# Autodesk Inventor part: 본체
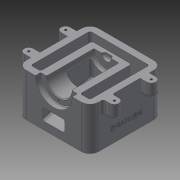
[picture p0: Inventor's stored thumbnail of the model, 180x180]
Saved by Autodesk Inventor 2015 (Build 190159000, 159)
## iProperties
Created: 2022-03
Part Number: 본체
Material: 일반
Document SubType Name: Modeling
Designer: pc-04
Density: 1 g/cm^3
Appearance: 기본값
Author: pc-04
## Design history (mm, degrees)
sketch "스케치1"
  geometry: L1 (-42, 55)-(42, 55); L2 (55, 42)-(55, -42); L3 (42, -55)-(-42, -55); L4 (-55, -42)-(-55, 42); L5 (-55, 55)-(55, -55); L6 (55, 55)-(-55, -55); A1 r 13 centre (-42, 42) between (-42, 55) and (-55, 42); A2 r 13 centre (42, 42) between (55, 42) and (42, 55); A3 r 13 centre (-42, -42) between (-55, -42) and (-42, -55); A4 r 13 centre (42, -42) between (42, -55) and (55, -42); 1 further point
  constraints: 12 end point, 8 point on circle, 8 point on line, 8 tangent, 4 centre point, 3 equal radius, 2 midpoint, 2 parallel, 1 horizontal, 1 perpendicular
  dimensions: "d0" = 110 distance of L5.start L6.start; "d1" = 110 distance of L6.end L5.start; "d2" = 13 radius of A1
extrude "돌출1" new body sketch "스케치1" distance "d3" = 65; taper "d4" = 0 deg
sketch "스케치2"
  geometry: L1 (-42, -55)-(42, -55) reference; L2 (42, 55)-(-42, 55) reference; L3 (42, -28)-(-42, -28); L4 (-42, 28)-(42, 28); L5 (-65, 28)-(65, 28); L6 (-65, -28)-(65, -28); L7 (55, -42)-(55, 42) reference; L8 (55, 35)-(55, 21); L9 (-55, 42)-(-55, -42) reference; L10 (-55, 35)-(-55, 21); L11 (-55, -21)-(-55, -35); L12 (55, -21)-(55, -35); L13 (-65, -35)-(-55, -35); L14 (55, -35)-(65, -35); L15 (-65, -21)-(-55, -21); L16 (55, -21)-(65, -21); L17 (-65, 35)-(-55, 35); L18 (55, 35)-(65, 35); L19 (-65, 21)-(-55, 21); L20 (55, 21)-(65, 21); A1 r 7 centre (-65, 28) between (-65, 35) and (-65, 21); A2 r 7 centre (-65, -28) between (-65, -21) and (-65, -35); A3 r 7 centre (65, 28) between (65, 21) and (65, 35); A4 r 7 centre (65, -28) between (65, -35) and (65, -21); 7 further points
  constraints: 32 end point, 8 point on circle, 8 point on line, 8 tangent, 6 coincident, 6 horizontal, 6 midpoint, 4 centre point, 2 parallel, 2 vertical alignment
  dimensions: "d6" = 83 distance between parallel lines of L2 L3; "d7" = 83 distance between parallel lines of L1 L4; "d8" = 130 distance of L5.start L5.end; "d9" = 130 distance of L6.start L6.end; "d10" = 14 diameter of A1; "d11" = 14 diameter of A2; "d12" = 14 diameter of A3; "d13" = 14 diameter of A4; "d14" = 90 deg angle of L18 L7; "d15" = 90 deg angle of L16 L7; "d16" = 34 distance between parallel lines of L20 L2; "d17" = 90 distance between parallel lines of L14 L2; "d18" = 13 distance from line of L4.end L7; "d19" = 13 distance from line of L3.start L7; "d20" = 55 distance from line of point (0, 28) L7; "d21" = 55 distance from line of point (0, -28) L7
extrude "돌출2" join sketch "스케치2" distance "d22" = 20; taper "d23" = 0 deg
sketch "스케치3"
  geometry: L1 (42, 55)-(-42, 55) reference; L2 (-42, -55)-(42, -55) reference; L3 (-55, 21)-(-55, -21) reference; L4 (55, -21)-(55, 21) reference; L5 (42, 45)-(-42, 45); L6 (45, -42)-(45, 42); L7 (-45, 42)-(-45, -42); L8 (27, 33)-(-27, 33); L9 (30, -42)-(30, 30); L10 (-30, 30)-(-30, -42); L11 (-42, -45)-(-33, -45); L12 (33, -45)-(42, -45); A1 r 3 centre (-42, 42) between (-42, 45) and (-45, 42); A2 r 3 centre (42, 42) between (45, 42) and (42, 45); A3 r 3 centre (-27, 30) between (-27, 33) and (-30, 30); A4 r 3 centre (27, 30) between (30, 30) and (27, 33); A5 r 3 centre (-42, -42) between (-45, -42) and (-42, -45); A6 r 3 centre (-33, -42) between (-33, -45) and (-30, -42); A7 r 3 centre (33, -42) between (30, -42) and (33, -45); A8 r 3 centre (42, -42) between (42, -45) and (45, -42); 1 further point
  constraints: 16 end point, 16 point on circle, 16 tangent, 8 centre point, 8 parallel, 7 equal radius
  dimensions: "d24" = 10 distance between parallel lines of L1 L5; "d26" = 10 distance between parallel lines of L4 L6; "d27" = 10 distance between parallel lines of L3 L7; "d28" = 22 distance between parallel lines of L1 L8; "d29" = 25 distance between parallel lines of L4 L9; "d30" = 25 distance between parallel lines of L3 L10; "d31" = 100 distance between parallel lines of L1 L12; "d32" = 100 distance between parallel lines of L1 L11; "d33" = 3 radius of A1
extrude "돌출3" cut sketch "스케치3" stored distance "d34" = 20; taper "d35" = 0 deg
sketch "스케치4"
  geometry: A1 r 7 centre (-65, 28) between (-65, 35) and (-65, 21) reference; A2 r 7 centre (-65, -28) between (-65, -21) and (-65, -35) reference; A3 r 7 centre (65, 28) between (65, 21) and (65, 35) reference; A4 r 7 centre (65, -28) between (65, -35) and (65, -21) reference; 5 further points
  constraints: 4 coincident
hole "구멍1" sketch "스케치4" at (-65, 28), (-65, -28), (65, 28), (65, -28) diameter "d36" = 3.242; stored, may be unused: countersink angle "d40" = 90 deg, drill point angle "d42" = 118 deg; dims "d37" = 9, "d38" = 4, "d39" = 2, "d41" = 11
sketch "스케치5"
  geometry: L1 (-42, 65)-(30, 65) reference; L2 (30, 0)-(-42, 0) reference; L3 (-55, 0)-(-55, 65) reference; L4 (55, 0)-(55, 65) reference; L5 (55, 65)-(-55, 65); L6 (-55, 65)-(-47, 65); L7 (-47, 65)-(-47, 37); L8 (-47, 37)-(-55, 37); L9 (-55, 37)-(-55, 65); L10 (-47, 65)-(25, 65); L11 (25, 65)-(25, 46); L12 (25, 46)-(-47, 46); L13 (-47, 46)-(-47, 65); 1 further point
  constraints: 18 end point, 4 parallel, 3 horizontal, 2 perpendicular
  dimensions: "d43" = 8 distance of L7.end L8.end; "d44" = 72 distance of L11.end L12.end; "d45" = 56 diameter of L8 L5; "d47" = 38 diameter of L12 L5
revolve "회전1" sketch "스케치5" stored, may be unused: angle "d48" = 90 deg
sketch "스케치6"
  geometry: L1 (-19, 0)-(19, 0) reference; C1 r 7.5 at (0, 0); 1 further point
  constraints: 1 centre point, 1 midpoint
  dimensions: "d49" = 15 diameter of C1
extrude "돌출4" cut sketch "스케치6" distance "d50" = 4; taper "d51" = -30 deg
sketch "스케치7" dims "d52" = 46
  geometry: L1 (-5.191, 0)-(5.191, 0) reference; 3 further points
  constraints: 1 vertical alignment, 2 other
  dimensions: "d53" = 23 distance from line of L1 point (0, -23); "d54" = 0 distance from line of point (0, 0) L1; "d55" = 5.1906 distance of L1.end point (0, 0)
hole "구멍2" sketch "스케치7" at (0, -23) diameter "d56" = 3.242; stored, may be unused: countersink angle "d60" = 90 deg, drill point angle "d62" = 118 deg; dims "d57" = 9, "d58" = 4, "d59" = 2, "d61" = 11
sketch "스케치8"
  geometry: L1 (55, 0)-(55, 65) reference; L2 (-55, 0)-(-55, 65) reference; L3 (30, 0)-(-42, 0) reference; L4 (25, 65)-(-47, 65) reference; L5 (33, 30)-(-42.776, 9.696); L6 (-45, 0)-(-45, 65); L7 (-45, 6.798)-(-45, 0); L8 (-45, 0)-(33, 0); L9 (33, 0)-(33, 30); L10 (16.776, 30.829)-(-55, 11.597); L11 (-21.224, 38.247)-(-55, 29.197); L12 (-19, 41.145)-(-19, 65); L13 (19, 33.727)-(19, 65); L14 (19, 65)-(-19, 65); L15 (-55, 29.197)-(-55, 11.597); A1 r 3 centre (-42, 6.798) between (-42.776, 9.696) and (-45, 6.798); A2 r 3 centre (16, 33.727) between (16.776, 30.829) and (19, 33.727); A3 r 3 centre (-22, 41.145) between (-21.224, 38.247) and (-19, 41.145); 2 further points
  constraints: 22 end point, 6 parallel, 6 point on circle, 6 tangent, 5 point on line, 3 centre point, 2 collinear, 2 equal radius, 2 perpendicular
  dimensions: "d71" = 15 deg angle of L3 L5; "d72" = 28.11338 distance from line of L1.end L5; "d73" = 65 distance from line of L6.end L3; "d76" = 5 distance between parallel lines of L5 L10; "d77" = 17 distance between parallel lines of L10 L11; "d78" = 36 distance between parallel lines of L2 L12; "d79" = 38 distance between parallel lines of L12 L13; "d80" = 3 radius of A1; "d81" = 0 distance between parallel lines of L4 L14
extrude "돌출5" cut sketch "스케치8" stored distance "d74" = 60; taper "d75" = 0 deg
extrude "돌출6" cut sketch "스케치8" stored distance "d82" = 34; taper "d83" = 0 deg
fillet "모깎기1" dims "d84" = 3
chamfer "모따기1" distance "d85" = 1; stored, may be unused: second distance "d86" = 2, angle "d87" = 45 deg
fillet "모깎기2" dims "d88" = 3
fillet "모깎기3" dims "d89" = 3
sketch "스케치9"
  geometry: L1 (0, -13)-(-65, -13) reference; 2 further points
  constraints: 1 other
  dimensions: "d90" = 55 distance from line of L1 point (-20, 42); "d91" = 20 distance of point (0, 42) point (-20, 42)
feature "엠보싱1" sketch "스케치9" dims "d0" = 110, "d1" = 110, "d2" = 13, "d7" = 83, "d8" = 130, "d10" = 14, "d12" = 14, "d14" = 90 deg, "d16" = 34, "d18" = 13, "d20" = 55, "d92" = 0.5, "d93" = 0
node "솔리드1"
